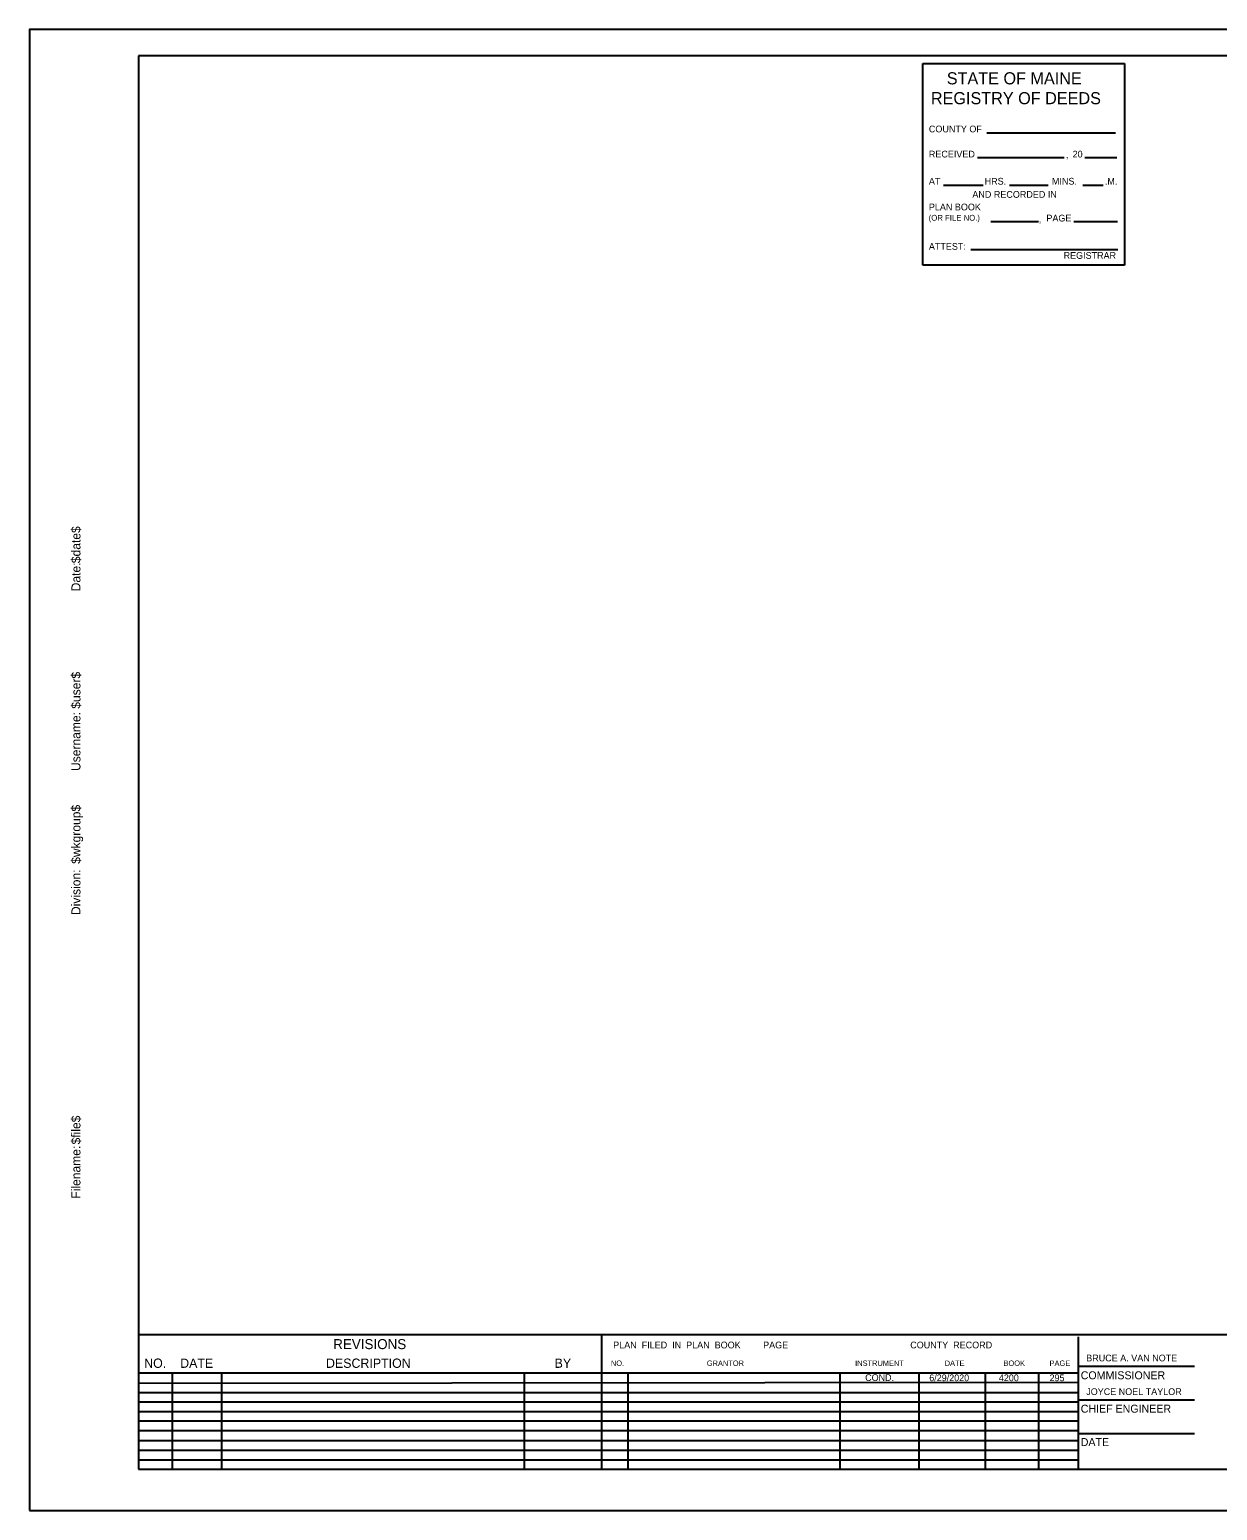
# Model space of a CAD drawing. Extents: x -415 to 435, y -303 to 247.
# Drawn here: x -415 to 26, y -303 to 247 of the extents above; entities that cross this region are included whole.
import ezdxf

# ---------------------------------------------------------------- set-up
doc = ezdxf.new("R2010")
doc.units = 0
for name, color, linetype in [('Border', 7, 'Continuous'), ('EX ROW NOTES', 7, 'Continuous'), ('PLOT BOUNDARY', 7, 'Continuous'), ('PRPTY SETUPS', 7, 'Continuous')]:
    doc.layers.add(name, color=color, linetype=linetype)

msp = doc.modelspace()

# ---------------------------------------------------------------- linework, layer by layer
at = {"layer": 'Border'}
for p, q in [((425, 237.5), (-375, 237.5)), ((-375, 237.5), (-375, -287.5)), ((-375, -237.49), (425, -237.49)), ((-202.99, -237.49), (-202.99, -287.5)), ((-25.83, -238.29), (-25.83, -287.5)), ((-375, -251.67), (-25.83, -251.67)), ((-362.5, -251.67), (-362.5, -287.5)), ((-344.13, -251.67), (-344.13, -287.5)), ((-231.63, -251.67), (-231.63, -287.5)), ((-193.15, -251.67), (-193.15, -287.5)), ((-114.41, -251.67), (-114.41, -287.5)), ((-84.88, -287.5), (-84.88, -251.67)), ((-60.27, -287.5), (-60.27, -251.67)), ((-40.59, -251.67), (-40.59, -287.5)), ((-25.83, -249.2), (17.41, -249.2)), ((-375, -255.6), (-25.83, -255.22)), ((-375, -258.96), (-25.83, -258.96)), ((-375, -262.5), (-26.02, -262.5)), ((-25.83, -261.7), (17.41, -261.7)), ((-375, -266.04), (-25.83, -266.04)), ((-375, -269.59), (-25.83, -269.59)), ((-375, -273.13), (-25.63, -273.13)), ((-25.83, -274.2), (17.41, -274.2)), ((-375, -276.87), (-25.83, -276.87)), ((-375, -280.41), (-25.83, -280.41)), ((-375, -283.96), (-25.83, -283.96)), ((-375, -287.5), (425, -287.5))]:
    msp.add_line(p, q, dxfattribs=at)
at = {"layer": 'PLOT BOUNDARY'}
msp.add_lwpolyline([(-415.47, -302.8), (434.53, -302.8), (434.53, 247.2), (-415.47, 247.2)], close=True, dxfattribs=at)
at = {"layer": 'PRPTY SETUPS'}
for p, q in [((-83.55, 234.66), (-8.57, 234.66)), ((-83.55, 159.68), (-83.55, 234.66)), ((-8.57, 234.66), (-8.57, 159.68)), ((-59.74, 208.89), (-12.01, 208.89)), ((-63.28, 199.73), (-31.05, 199.73)), ((-23.33, 199.73), (-11.47, 199.73)), ((-75.86, 189.45), (-61.07, 189.45)), ((-51.32, 189.45), (-36.96, 189.45)), ((-24.13, 189.45), (-16.58, 189.45)), ((-58.25, 175.94), (-40.54, 175.94)), ((-27.42, 175.94), (-11.23, 175.94)), ((-65.68, 165.48), (-11.14, 165.48)), ((-8.57, 159.68), (-83.55, 159.68))]:
    msp.add_line(p, q, dxfattribs=at)

# ---------------------------------------------------------------- texts
at = {"layer": 'Border'}
for s, height, rotation, p in [('$date$', 3.348, 90, (-396.58, 49.03)), ('Date:', 3.348, 90, (-396.58, 38.58)), ('$user$', 3.348, 90, (-396.58, -5.04)), ('Username:', 3.348, 90, (-396.58, -28.16)), ('$wkgroup$', 3.348, 90, (-396.58, -62.65)), ('Division:', 3.348, 90, (-396.58, -81.67)), ('$file$', 3.348, 90, (-396.58, -166.87)), ('Filename:', 3.348, 90, (-396.58, -187.01)), ('REVISIONS', 3.726, 360, (-302.65, -242.9)), ('NO.', 3.445, 360, (-372.89, -249.85)), ('DATE', 3.445, 360, (-359.52, -249.85)), ('DESCRIPTION', 3.4449, 360, (-305.33, -249.85)), ('BY', 3.445, 360, (-220.38, -249.85)), ('COMMISSIONER', 2.9528, 360, (-24.87, -254.1)), ('CHIEF ENGINEER', 2.9528, 360, (-24.87, -266.5)), ('DATE', 2.953, 360, (-24.87, -278.9))]:
    msp.add_text(s, height=height, rotation=rotation, dxfattribs=at).set_placement(p)
for s, height, p in [('PLAN  FILED  IN  PLAN  BOOK         PAGE', 2.4992, (-198.6, -242.62)), ('COUNTY  RECORD', 2.4992, (-88.23, -242.62)), ('NO.', 2, (-199.45, -249.13)), ('GRANTOR', 2, (-163.82, -249.13)), ('INSTRUMENT', 2, (-108.7, -249.13)), ('DATE', 2, (-75.43, -249.13)), ('BOOK', 2, (-53.58, -249.13)), ('PAGE', 2, (-36.46, -249.13)), ('BRUCE A. VAN NOTE', 2.5, (-22.83, -247.45)), ('JOYCE NOEL TAYLOR', 2.5, (-22.83, -259.95))]:
    msp.add_text(s, height=height, dxfattribs=at).set_placement(p)
at = {"layer": 'EX ROW NOTES'}
for s, p in [('COND.', (-104.97, -254.72)), ('6/29/2020', (-81.15, -254.8)), ('4200', (-55.29, -254.8)), ('295', (-36.46, -254.8))]:
    msp.add_text(s, height=2.49, dxfattribs=at).set_placement(p)
at = {"layer": 'PRPTY SETUPS'}
for s, height, p in [('STATE OF MAINE', 4.5, (-74.65, 226.87)), ('REGISTRY OF DEEDS', 4.5, (-80.56, 219.49)), ('COUNTY OF', 2.5, (-81.3, 209.05)), ('RECEIVED', 2.5, (-81.3, 199.71)), (',', 2.61, (-30.43, 199.48)), ('20', 2.5, (-27.89, 199.71)), ('AT', 2.5, (-81.3, 189.64)), ('AND RECORDED IN', 2.5, (-65.14, 184.74)), ('HRS.', 2.5, (-60.58, 189.64)), ('MINS.', 2.5, (-35.57, 189.64)), ('.M.', 2.5, (-15.91, 189.64)), ('PLAN BOOK ', 2.5, (-81.3, 180.07)), ('(OR FILE NO.)', 2.1531, (-81.37, 176.24)), (',', 2.61, (-40.49, 175.61)), ('PAGE', 2.5, (-37.63, 175.94)), ('ATTEST:', 2.5, (-81.3, 165.42)), ('REGISTRAR', 2.5, (-31.24, 162.07))]:
    msp.add_text(s, height=height, dxfattribs=at).set_placement(p)

doc.saveas('drawing.dxf')
